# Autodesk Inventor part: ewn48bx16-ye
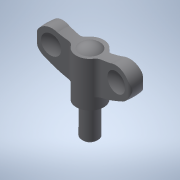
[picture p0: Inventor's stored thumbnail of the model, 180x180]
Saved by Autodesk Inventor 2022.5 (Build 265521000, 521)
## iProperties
Created: 2017-05
Part Number: ewn48bx16-ye
Material: 一般
Document SubType Name: Modeling
Designer: imaocorp
Density: 1 g/cm^3
Appearance: 既定
Author: imaocorp
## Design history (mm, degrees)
node "ewn48bx16-ye.x_t1"
node "ewn48bx16-ye"
node "Base1"
